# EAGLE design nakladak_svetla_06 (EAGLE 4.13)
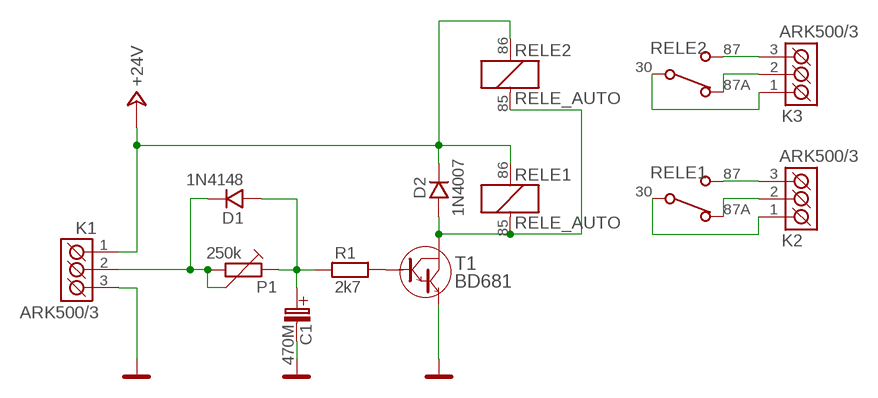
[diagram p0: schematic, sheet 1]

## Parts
C1  470M  470M/25V  [C_EL_5]
D1  1N4148  1N4148_7,5  [D-7,5]
D2  1N4007  1N4007_10  [D-10]
K1  ARK500/3  [ARK500/3]
K2  ARK500/3  [ARK500/3]
K3  ARK500/3  [ARK500/3]
P1  250k  PT-10_V-LEZ  [PT10V]
R1  2k7  R_7,5  [R-7,5]
RELE1  RELE_AUTO  [RELE_AUTO]
RELE2  RELE_AUTO  [RELE_AUTO]
T1  BD681  BD681_STOJ  [TO-126S]

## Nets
+24V: D2.K K1.1(K1) RELE1.86(REL:C+) RELE2.86(REL:C+)
GND: C1.C-(C_EL-) K1.3(K3) T1.1(E)
N$1: D1.K K1.2(K2) P1.2 P1.3
N$2: C1.C+(C_EL+) D1.A P1.1 R1.1
N$3: D2.A RELE1.85(REL:C-) RELE2.85(REL:C-) T1.2(C)
N$4: K2.1(K1) RELE1.30(PREP:COM)
N$5: K2.3(K3) RELE1.87(PREP:NO)
N$6: K2.2(K2) RELE1.87A(PREP:NC)
N$7: R1.2 T1.3(B)
N$8: K3.3(K3) RELE2.87(PREP:NO)
N$9: K3.2(K2) RELE2.87A(PREP:NC)
N$10: K3.1(K1) RELE2.30(PREP:COM)

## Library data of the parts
C1 = #PaJa_C-el:470M/25V
D1 = #PaJa_17:1N4148: Univerzalni dioda - 0,15A, 75V
D2 = #PaJa_17:1N4007: Usmernovaci dioda - 1A, 1000V
K1-K3 = #PaJa_17:ARK500/3: Svorkovnice - roztec 5mm - trojita
P1 = #PaJa_17:PT-10: Trimr - 10,3mm
R1 = #PaJa_17:R: Rezistor
RELE1 RELE2 = #PaJa_17:RELE_AUTO: RELE - 1x prepinaci, 12V max. spinany proud = 40A
T1 = #PaJa_17:BD681

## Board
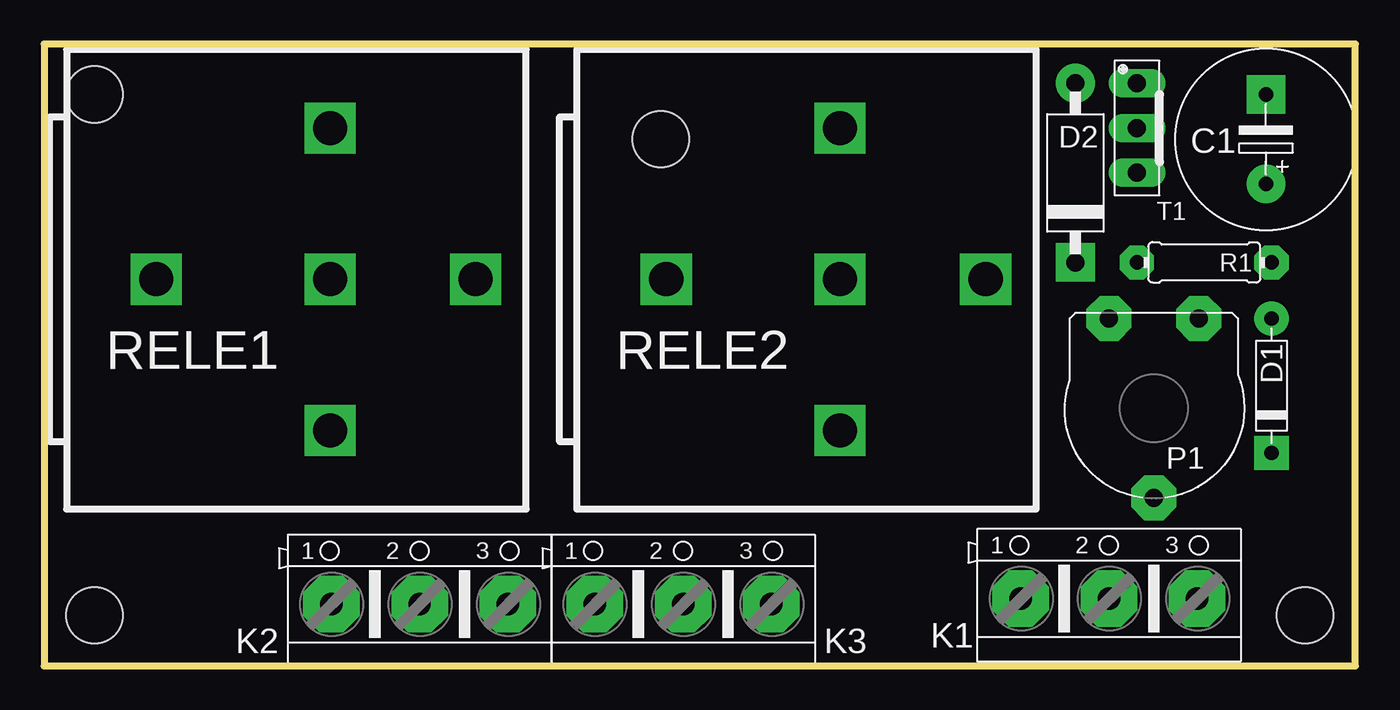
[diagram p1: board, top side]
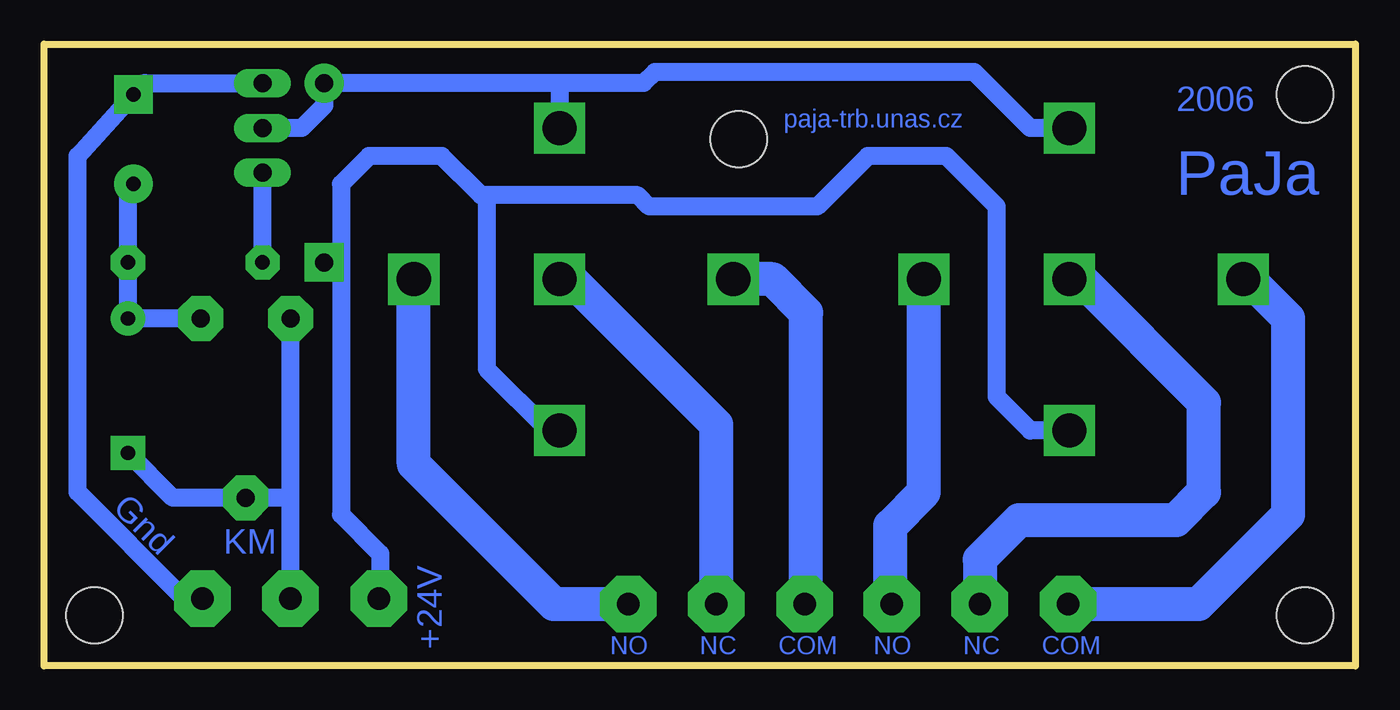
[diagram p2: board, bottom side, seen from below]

Size 74.28 x 35.23 mm. Coordinates in mm from the lower left corner, seen from the top.
Outline: 0,0 74.28,0 74.28,35.23 0,35.23 0,0
Copper layers (1*16): Top 0.035mm / dielectric 1.5mm / Bottom 0.035mm
Design rules "default": minimum track width 10mil, minimum drill 24mil, track to track 8mil, track to pad 8mil, pad to pad 8mil, via to via 8mil, smd to smd 8mil, copper to edge 40mil, drill to drill 8mil, minimum pad ring 10mil, minimum via ring 8mil, stop-mask expansion 4mil, vias tented up to drill 0mil, thermal gap 10mil
Holes 3.2 mm at 2.86,2.86 71.44,2.86 2.86,32.38 34.92,29.84

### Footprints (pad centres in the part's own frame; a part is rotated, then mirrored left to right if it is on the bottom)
C_EL_5 = drill 0.813 pad 2.184 round: C+ -2.54,0 | drill 0.813 pad 2.184 square: C- 2.54,0
D-7,5 = drill 0.813 pad 1.93 round: A -3.81,0 | drill 0.813 pad 1.93 square: K 3.81,0
D-10 = drill 1.016 pad 2.184 round: A -5.08,0 | drill 1.016 pad 2.184 square: K 5.08,0
ARK500/3 = drill 1.27 pad 3.2 octagon: 1 -5,0; 2 0,0; 3 5,0
PT10V = drill 1.016 pad 2.54 octagon: 1 -2.54,-5.08; 2 2.54,-5.08; 3 0,5.08
R-7,5 = drill 0.813 pad 1.93 octagon: 1 -3.81,0; 2 3.81,0
RELE_AUTO = drill 1.93 pad 2.54 square: 30 0,7.938; 85 8.572,-1.905; 86 -8.572,-1.905; 87 0,-10.16; 87A 0,-1.905
TO-126S = drill 1.016 pad 1.6 long: 1 -2.54,0; 2 0,0; 3 2.54,0

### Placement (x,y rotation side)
C1  69.22,29.84 90 top
D1  69.53,15.88 270 top
D2  58.42,27.94 270 top
K1  60.33,3.81 0 top
K2  21.27,3.49 0 top
K3  36.2,3.49 0 top
P1  62.87,14.61 180 top
R1  65.72,22.86 180 top
RELE1  14.29,21.91 90 top
RELE2  43.18,21.91 90 top
T1  61.91,30.48 270 top

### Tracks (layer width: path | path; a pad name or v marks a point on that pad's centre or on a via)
+24V
  Bottom 1.016: RELE1.86 18.41,13.34 20.32,15.24 20.32,26.04 23.18,28.89 27.62,28.89 30.48,26.04 40.01,26.04 40.64,26.67 49.21,26.67 | 49.21,26.67 49.21,16.83 45.72,13.34 RELE2.86 | 49.21,26.67 49.53,26.67 51.75,28.89 55.88,28.89 57.47,27.3 57.47,22.86 | K1.1 55.33,4.05 55.24,4.13 55.24,6.35 57.47,8.57 57.47,22.86 | 57.47,22.86 D2.K
GND
  Bottom 1.016: K1.3 66.36,3.81 72.39,9.84 72.39,28.89 C1.C- 68.58,33.02 T1.1
N$1
  Bottom 1.016: K1.2 60.33,9.53 | 60.33,9.53 P1.2 | 60.33,9.53 P1.3 66.99,9.53 D1.K
N$2
  Bottom 1.016: P1.1 D1.A R1.1 69.53,26.99 C1.C+
N$3
  Bottom 1.016: T1.2 59.69,30.48 58.42,31.75 D2.A 45.09,33.02 | RELE1.85 18.41,30.48 21.59,33.66 39.69,33.66 40.32,33.02 45.09,33.02 | 45.09,33.02 RELE2.85
N$4
  Bottom 1.93: RELE1.30 6.03,21.91 3.81,19.68 3.81,8.57 8.89,3.49 K2.1
N$5
  Bottom 1.93: RELE1.87 24.45,9.84 26.35,7.94 26.35,3.81 26.27,3.73 K2.3
N$6
  Bottom 1.93: RELE1.87A 15.56,21.91 8.57,14.92 8.57,9.84 10.16,8.26 19.05,8.26 21.27,6.03 K2.2
N$7
  Bottom 1.016: R1.2 T1.3
N$8
  Bottom 1.93: RELE2.87 53.34,11.43 45.4,3.49 K3.3
N$9
  Bottom 1.93: RELE2.87A 44.45,21.91 36.2,13.65 K3.2
N$10
  Bottom 1.93: RELE2.30 33.02,21.91 31.11,20 31.11,3.57 K3.1

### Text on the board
Bottom: 2006 | paja-trb.unas.cz | PaJa | Gnd | KM | COM | NC | NO | COM | NC | NO | +24V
